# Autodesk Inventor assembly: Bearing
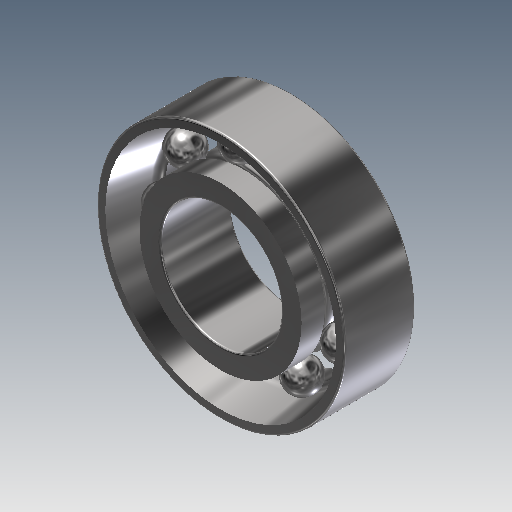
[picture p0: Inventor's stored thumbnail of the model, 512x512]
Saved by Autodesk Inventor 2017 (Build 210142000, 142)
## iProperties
Created: 2019-02
Part Number: Bearing
Document SubType Name: Assembly
Designer: user
Mass: 34.9637 g
Surface Area: 47.3243 cm^2
Volume: 4.45397 cm^3
Density: 7.85 g/cm^3
ClientObjectVersion: 1
Author: user
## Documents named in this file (2)
- C:\Users\user\Documents\EIA\Cursos\Diseño asistido por computador\Clase 7 Dynamic simulation\Ensamble reductor de velocidad\Ensamble\Design Accelerator\Bearing2.iam
- C:\Users\user\Documents\Inventor\Content Center Files\R2017\en-US\BS 292 (II)\BS 292_ Part 1 - 7003 - 17 x 35 x 10.ipt
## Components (1 placed, 1 different names)
1. BS 292: Part 1 (II) - Metric 7003 - 17 x 35 x 10:1
